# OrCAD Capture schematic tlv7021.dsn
size A
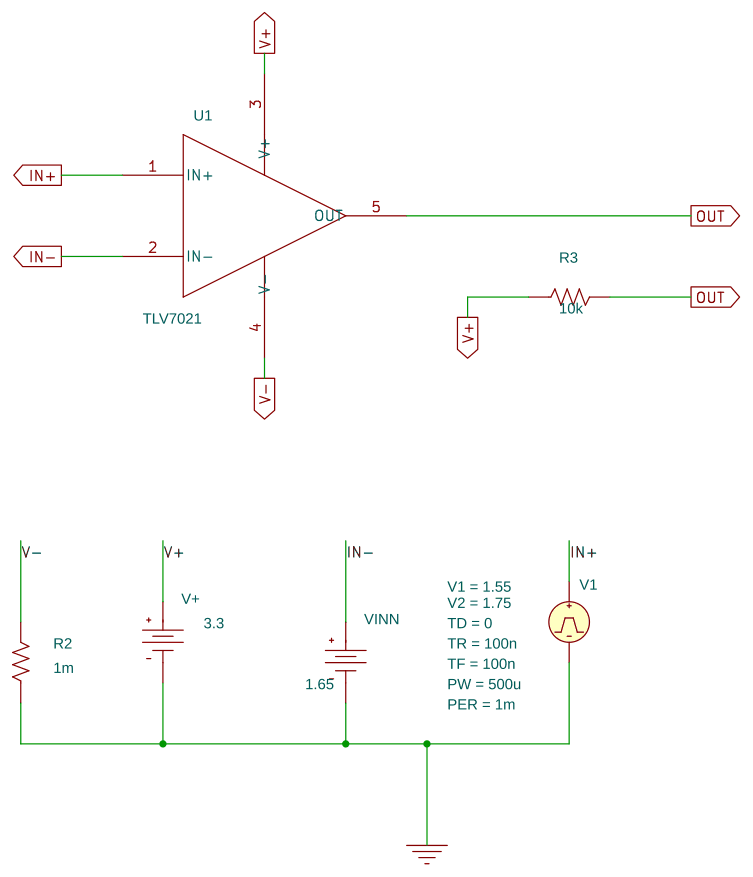
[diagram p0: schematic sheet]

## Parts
R2  1m  [AXRC05]
R3  10k  [AXRC05]
U1  TLV7021
V1  VPULSE
V+  VDC
VINN  VDC

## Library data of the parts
R2 R3 = R
U1 = TLV7021_3
V1 = VPULSE: PER: 1m; PW: 500u; TD: 0; TF: 100n; TR: 100n; V1: 1.55; V2: 1.75
V+ = VDC: DC: 3.3
VINN = VDC: DC: 1.65

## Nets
0: R2.1 V1.2(-) V+.1(-) VINN.1(-)
IN+: U1.1(IN+) V1.1(+)
IN-: U1.2(IN-) VINN.0(+)
OUT: R3.2 U1.5(OUT)
V+: R3.1 U1.3(V+) V+.0(+)
V-: R2.2 U1.4(V-)
